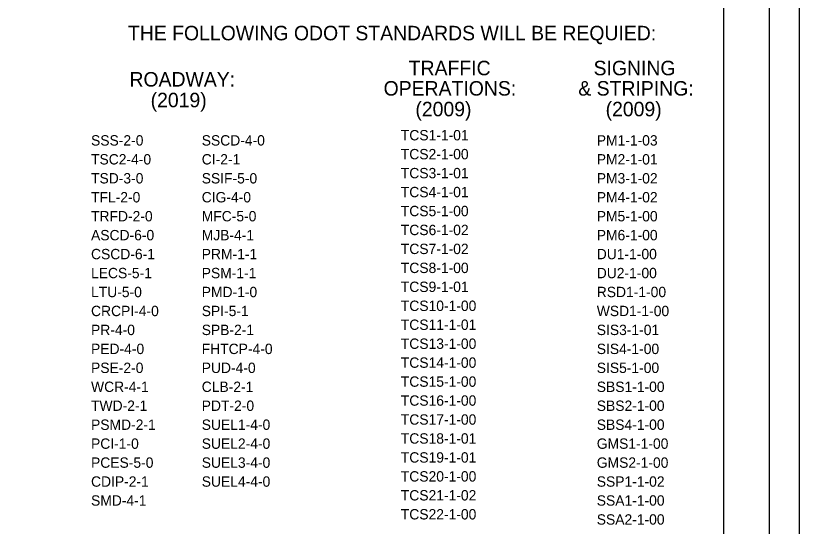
# Model space of a CAD drawing. Extents: x 11.3 to 109.4, y -18.4 to 58.
# Drawn here: x 64.37 to 83.28, y 34 to 46.33 of the extents above; entities that cross this region are included whole.
import ezdxf

# ---------------------------------------------------------------- set-up
doc = ezdxf.new("R2010")
doc.units = 0
for name, color, linetype in [('PR_Improvements_Txt', 7, 'Continuous'), ('SHT_Plot_Shape_Full', 7, 'Continuous'), ('SHT_Plot_Shape_Half', 7, 'Continuous'), ('SHT_Sheet_Border', 7, 'Continuous')]:
    doc.layers.add(name, color=color, linetype=linetype)

msp = doc.modelspace()

# ---------------------------------------------------------------- linework, layer by layer
at = {"layer": 'SHT_Plot_Shape_Full'}
msp.add_lwpolyline([(11.276, 57.98), (83.276, 57.98), (83.276, 9.98), (11.276, 9.98)], close=True, dxfattribs=at)
at = {"layer": 'SHT_Plot_Shape_Half'}
msp.add_lwpolyline([(14.551, 56.33), (82.551, 56.33), (82.551, 12.33), (14.551, 12.33)], close=True, dxfattribs=at)
at = {"layer": 'SHT_Sheet_Border'}
msp.add_lwpolyline([(81.451, 13.33), (18.451, 13.33), (18.451, 55.33), (81.451, 55.33)], close=True, dxfattribs=at)

# ---------------------------------------------------------------- texts
at = {"layer": 'PR_Improvements_Txt'}
for s, height, p in [('THE FOLLOWING ODOT STANDARDS WILL BE REQUIED:', 0.35, (67.081, 45.733)), ('TRAFFIC', 0.35, (73.854, 44.889)), ('SIGNING', 0.35, (78.313, 44.889)), ('ROADWAY:', 0.35, (67.118, 44.617)), ('OPERATIONS:', 0.35, (73.248, 44.399)), ('& STRIPING:', 0.35, (77.945, 44.399)), ('(2019)', 0.35, (67.628, 44.117)), ('(2009)', 0.35, (74.015, 43.899)), ('(2009)', 0.35, (78.603, 43.899)), ('TCS1-1-01', 0.25, (73.664, 43.318)), ('SSS-2-0', 0.25, (66.191, 43.193)), ('SSCD-4-0', 0.25, (68.861, 43.193)), ('PM1-1-03', 0.25, (78.39, 43.193)), ('TCS2-1-00', 0.25, (73.664, 42.861)), ('TSC2-4-0', 0.25, (66.191, 42.736)), ('CI-2-1', 0.25, (68.861, 42.736)), ('PM2-1-01', 0.25, (78.39, 42.736)), ('TCS3-1-01', 0.25, (73.664, 42.403)), ('TSD-3-0', 0.25, (66.191, 42.278)), ('SSIF-5-0', 0.25, (68.861, 42.278)), ('PM3-1-02', 0.25, (78.39, 42.278)), ('TCS4-1-01', 0.25, (73.664, 41.946)), ('TFL-2-0', 0.25, (66.191, 41.821)), ('CIG-4-0', 0.25, (68.861, 41.821)), ('PM4-1-02', 0.25, (78.39, 41.821)), ('TRFD-2-0', 0.25, (66.191, 41.363)), ('MFC-5-0', 0.25, (68.861, 41.363)), ('TCS5-1-00', 0.25, (73.664, 41.488)), ('PM5-1-00', 0.25, (78.39, 41.363)), ('TCS6-1-02', 0.25, (73.664, 41.031)), ('ASCD-6-0', 0.25, (66.191, 40.906)), ('MJB-4-1', 0.25, (68.861, 40.906)), ('PM6-1-00', 0.25, (78.39, 40.906)), ('CSCD-6-1', 0.25, (66.191, 40.449)), ('PRM-1-1', 0.25, (68.861, 40.449)), ('TCS7-1-02', 0.25, (73.664, 40.574)), ('DU1-1-00', 0.25, (78.39, 40.449)), ('TCS8-1-00', 0.25, (73.664, 40.116)), ('LECS-5-1', 0.25, (66.191, 39.991)), ('PSM-1-1', 0.25, (68.861, 39.991)), ('DU2-1-00', 0.25, (78.39, 39.991)), ('TCS9-1-01', 0.25, (73.664, 39.659)), ('LTU-5-0', 0.25, (66.191, 39.534)), ('PMD-1-0', 0.25, (68.861, 39.534)), ('RSD1-1-00', 0.25, (78.39, 39.534)), ('CRCPI-4-0', 0.25, (66.191, 39.076)), ('SPI-5-1', 0.25, (68.861, 39.076)), ('TCS10-1-00', 0.25, (73.664, 39.201)), ('WSD1-1-00', 0.25, (78.39, 39.076)), ('TCS11-1-01', 0.25, (73.664, 38.744)), ('PR-4-0', 0.25, (66.191, 38.619)), ('SPB-2-1', 0.25, (68.861, 38.619)), ('SIS3-1-01', 0.25, (78.39, 38.619)), ('PED-4-0', 0.25, (66.191, 38.161)), ('FHTCP-4-0', 0.25, (68.861, 38.161)), ('TCS13-1-00', 0.25, (73.664, 38.286)), ('SIS4-1-00', 0.25, (78.39, 38.161)), ('TCS14-1-00', 0.25, (73.664, 37.829)), ('PSE-2-0', 0.25, (66.191, 37.704)), ('PUD-4-0', 0.25, (68.861, 37.704)), ('SIS5-1-00', 0.25, (78.39, 37.704)), ('TCS15-1-00', 0.25, (73.664, 37.371)), ('WCR-4-1', 0.25, (66.191, 37.246)), ('CLB-2-1', 0.25, (68.861, 37.246)), ('SBS1-1-00', 0.25, (78.39, 37.246)), ('TCS16-1-00', 0.25, (73.664, 36.914)), ('TWD-2-1', 0.25, (66.191, 36.789)), ('PDT-2-0', 0.25, (68.861, 36.789)), ('SBS2-1-00', 0.25, (78.39, 36.789)), ('TCS17-1-00', 0.25, (73.664, 36.456)), ('PSMD-2-1', 0.25, (66.191, 36.331)), ('SUEL1-4-0', 0.25, (68.861, 36.331)), ('SBS4-1-00', 0.25, (78.39, 36.331)), ('PCI-1-0', 0.25, (66.191, 35.874)), ('SUEL2-4-0', 0.25, (68.861, 35.874)), ('TCS18-1-01', 0.25, (73.664, 35.999)), ('GMS1-1-00', 0.25, (78.39, 35.874)), ('TCS19-1-01', 0.25, (73.664, 35.541)), ('PCES-5-0', 0.25, (66.191, 35.416)), ('SUEL3-4-0', 0.25, (68.861, 35.416)), ('GMS2-1-00', 0.25, (78.39, 35.416)), ('CDIP-2-1', 0.25, (66.191, 34.959)), ('SUEL4-4-0', 0.25, (68.861, 34.959)), ('TCS20-1-00', 0.25, (73.664, 35.084)), ('SSP1-1-02', 0.25, (78.39, 34.959)), ('TCS21-1-02', 0.25, (73.664, 34.627)), ('SMD-4-1', 0.25, (66.191, 34.502)), ('SSA1-1-00', 0.25, (78.39, 34.502)), ('TCS22-1-00', 0.25, (73.664, 34.169)), ('SSA2-1-00', 0.25, (78.39, 34.044))]:
    msp.add_text(s, height=height, dxfattribs=at).set_placement(p)

doc.saveas('drawing.dxf')
